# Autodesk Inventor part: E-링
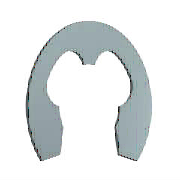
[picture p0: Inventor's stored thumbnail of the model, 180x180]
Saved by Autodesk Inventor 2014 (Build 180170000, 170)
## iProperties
IsCustomPart: 1
Created: 2012-02
Part Number: E-링
Material: 강철, 연강
Description: 일반용 테이퍼 및 줄어든 횡단면 리테이닝 링 - E-링 외부 시리즈 3CM1 리테이닝 링
Document SubType Name: Modeling
Standard: ANSI B27.7
Designer: mduedu
Standard Revision: 1999
Standards Organization: ANSI
Language: ko-KR
Size Designation: 6
Categories: <MemberInstance><Categories><Category DisplayName="샤프트 부품" InternalName="7f7aeb1f-a693-4053-b835-cee3144e0d98" Mnemonic="SHFT"><Category DisplayName="써클립" Inter
Density: 1 g/cm^3
Appearance: Blue - Wall Paint - Glossy
Author: mduedu
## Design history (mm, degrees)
sketch "스케치1"
  geometry: L1 (-0.485, 0.024)-(0, 0.024) reference; L2 (-3.206, 0)-(3.486, 0) reference; L3 (-2.223, -3.946)-(2.223, -3.946); L4 (0, 1.949)-(0, -3.479) reference; L5 (-2.91, -2.006)-(-2.435, -2.006); L6 (-0.485, -0.066)-(-0.485, 0.405); L7 (0, 2.574)-(2.53, 2.574); L8 (-2.223, -3.946)-(-3.022, -6.291); L9 (0, -0.551)-(-1.278, -0.551); L10 (2.223, -3.946)-(3.022, -6.291); L11 (2.91, -2.006)-(2.435, -2.006); L12 (0.485, -0.066)-(0.485, 0.405); C1 r 3 at (0, -2.976); A1 r 2.425 centre (0, -2.976) between (-2.297, -2.199) and (-2.223, -3.946); A2 r 0.485 centre (0, -0.066) between (-0.485, -0.066) and (0.485, -0.066); A3 r 5.55 centre (0, -2.976) between (4.27, -6.521) and (-4.27, -6.521); A4 r 3.88 centre (0, -2.976) between (-0.97, 0.78) and (-3.424, -1.15); A5 r 0.388 centre (-0.873, 0.405) between (-0.485, 0.405) and (-0.97, 0.78); A6 r 0.582 centre (-2.91, -1.424) between (-3.424, -1.15) and (-2.91, -2.006); A7 r 0.145 centre (-2.435, -2.152) between (-2.297, -2.199) and (-2.435, -2.006); A8 r 0.727 centre (-3.711, -6.057) between (-4.27, -6.521) and (-3.022, -6.291); A9 r 0.727 centre (3.711, -6.057) between (3.022, -6.291) and (4.27, -6.521); A10 r 2.425 centre (0, -2.976) between (2.223, -3.946) and (2.297, -2.199); A11 r 0.145 centre (2.435, -2.152) between (2.435, -2.006) and (2.297, -2.199); A12 r 0.582 centre (2.91, -1.424) between (2.91, -2.006) and (3.424, -1.15); A13 r 3.88 centre (0, -2.976) between (3.424, -1.15) and (0.97, 0.78); A14 r 0.388 centre (0.873, 0.405) between (0.97, 0.78) and (0.485, 0.405); 1 further point
  constraints: 30 point on circle, 20 end point, 15 centre point, 13 symmetric about line, 12 tangent, 8 point on line, 4 parallel, 2 coincident, 2 horizontal, 1 concentric, 1 perpendicular, 1 vertical alignment, 9 other
  dimensions: "d0" = 6 diameter of C1 (= WD); "d3" = 0.97 distance from line of A1.centre L3 (= 0.2 x ND); "d4" = 0.485 radius of A2 (= 0.1 x ND); "d5" = 11.1 diameter of A3 (= SD2); "d8" = 3.88 radius of A4 (= 0.8 x ND); "d9" = 0.97 distance from line of A1.centre L5 (= 0.2 x ND); "d10" = 0.388 radius of A5 (= 0.08 x ND); "d11" = 0.582 radius of A6 (= 0.12 x ND); "d12" = 0.1455 radius of A7 (= 0.03 x ND); "d13" = 0.7275 radius of A8 (= 0.15 x ND); "d14" = 2.425 distance from line of A1.centre L9 (= 0.5 x ND); "d15" = 2.425 radius of A1 (= 0.5 x ND)
extrude "본체" new body sketch "스케치1" distance "d16" = 0.6 (= SD); taper "d17" = 0 deg
workaxis "Work Axis1"
workaxis "Work Axis2"
workplane "Work Plane1"
body "Solid1"
other parameters: "ND" = 4.85 [user parameter; used in 14 equation terms], "SD" = 0.6 [user parameter; used in 1 equation term], "WD" = 6 (= WDMIN) [user parameter; used in 1 equation term], "d1" = 7.76 (= 1.6 x ND), "d2" = 4.85 (= ND), "SD2" = 11.1 [user parameter; used in 1 equation term], "d6" = 4.85 (= ND), "d7" = 0.7275 (= 0.15 x ND), "d18" = 0, "d19" = 0, "d27" = 0, "d28" = 0, "WDMIN" = 6 [user parameter; used in 1 equation term], "SNB" = 0.7 [user parameter], "WDMAX" = 7 [user parameter], "BUBRMI" = 1.2 [user parameter]
